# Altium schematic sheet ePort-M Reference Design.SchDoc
size A4; CheckedBy: AIoT事业部; Author: 工控机; DocumentNumber: 1; SheetNumber: 1; SheetTotal: 1; PageSetup: Record=PageOptions¦CenterHorizontal=True¦CenterVertical=True¦PrintScale=1.00¦XCorrection=1.00¦YCorrection=1.00¦PrintKind=0¦BorderSize=5000000¦LeftOffset=0¦BottomOffset=0¦Orientation=2¦PaperLength=1000¦PaperWidth=1000¦Scale=100¦PaperSource=7¦PrintQuality=600¦MediaType=1¦DitherType=10¦PrintScaleMode=1¦PaperKind=A4; DesignDate: 2023-2-18; CheckDate: 2023-2-18; SheetName: ePort-M参考设计电路; SheetVersion: Rev.A; SheetDescription: 集成PHY和网络变压器的RJ45座子; ProductName: 集成式RJ45座子; ProductModel: ePort-M
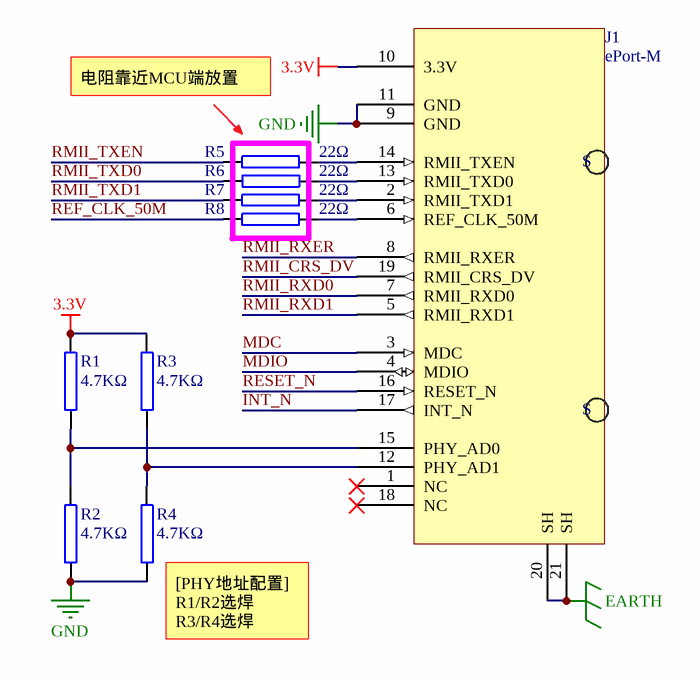
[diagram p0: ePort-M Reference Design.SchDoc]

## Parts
J1  ePort-M  [eport]
R1  4.7KΩ  [0402R]
R2  4.7KΩ  [0402R]
R3  4.7KΩ  [0402R]
R4  4.7KΩ  [0402R]
R5  22Ω  [0402R]
R6  22Ω  [0402R]
R7  22Ω  [0402R]
R8  22Ω  [0402R]

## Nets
3.3V: J1.10(3.3V) R1.1 R3.1
EARTH: J1.20(SH) J1.21(SH)
GND: J1.9(GND) J1.11(GND) R2.2 R4.2
INT_N: J1.17(INT_N)
MDC: J1.3(MDC)
MDIO: J1.4(MDIO)
REF_CLK_50M: R8.2
RESET_N: J1.16(RESET_N)
RMII_CRS_DV: J1.19(RMII_CRS_DV)
RMII_RXD0: J1.7(RMII_RXD0)
RMII_RXD1: J1.5(RMII_RXD1)
RMII_RXER: J1.8(RMII_RXER)
RMII_TXD0: R6.1
RMII_TXD1: R7.2
RMII_TXEN: R5.2
NetJ1_2: J1.2(RMII_TXD1) R7.1
NetJ1_6: J1.6(REF_CLK_50M) R8.1
NetJ1_12: J1.12(PHY_AD1) R3.2 R4.1
NetJ1_13: J1.13(RMII_TXD0) R6.2
NetJ1_14: J1.14(RMII_TXEN) R5.1
NetJ1_15: J1.15(PHY_AD0) R1.2 R2.1

Not connected (* = marked no-connect by the designer): J1 1(NC)* 18(NC)*

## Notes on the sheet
- 电阻靠近MCU端放置
- (near R4) [PHY地址配置]
  R1/R2选焊
  R3/R4选焊

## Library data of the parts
J1 = ePort-M: 百兆集成式RJ45插座
R1-R4 = 01.01.00003: RTT02472JTH,0402,RALEC,4.7KΩ,±5%,1/16W,; 名称: 电阻; 封装: 0402; 贴片和直插: SMT; 旧物料代码: 1.01.17.0019; 环保状态: RoHS2.0+REACH; 器件优选方案: 通用物料; 生产单位: PCS
R5-R8 = 01.01.00014: RTT02220JTH,0402,RALEC,22Ω,±5%,1/16W,; 名称: 电阻; 封装: 0402; 贴片和直插: SMT; 器件优选方案: 通用物料; 旧物料代码: 1.01.17.0023; 环保状态: RoHS2.0+REACH; 生产单位: PCS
